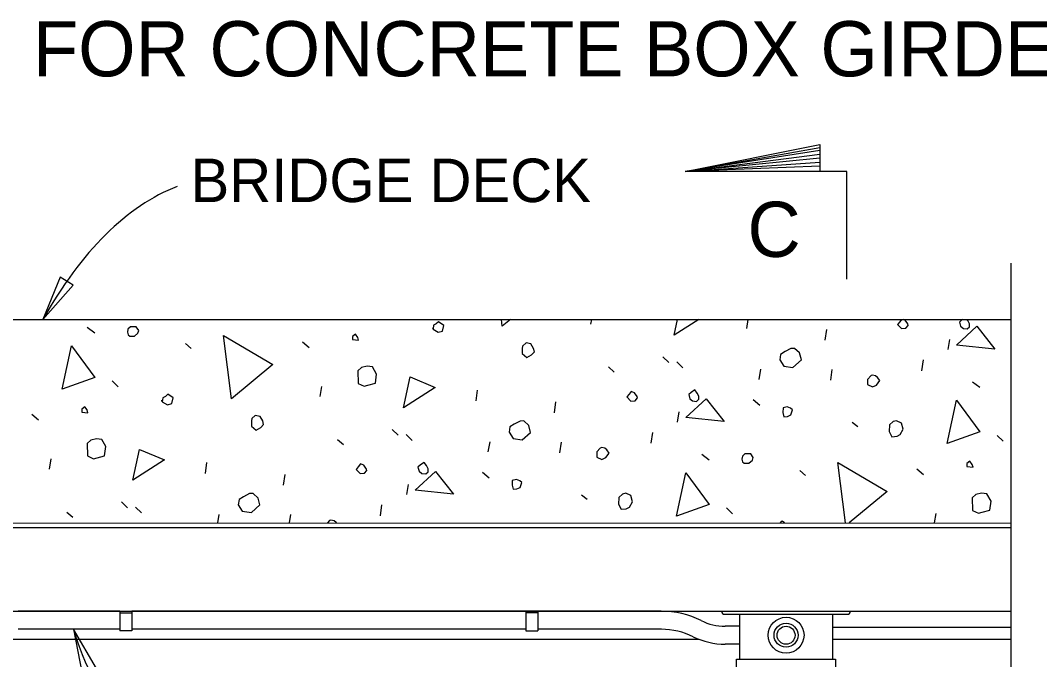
# Model space of a CAD drawing. Extents: x -1660015.2 to -1659984.9, y 2580594.2 to 2580616.7.
# Drawn here: x -1660010.005 to -1660006.46, y 2580602.872 to 2580605.097 of the extents above; entities that cross this region are included whole.
import ezdxf

# ---------------------------------------------------------------- set-up
doc = ezdxf.new("R2010")
doc.units = 0
for name, color, linetype in [('Default', 7, 'Continuous'), ('Miscellaneous', 7, 'Continuous'), ('Miscellaneous3', 7, 'Continuous'), ('PlotBorder_dp', 7, 'Continuous'), ('SheetLines_dp', 7, 'Continuous'), ('SteelGirder', 7, 'Continuous')]:
    doc.layers.add(name, color=color, linetype=linetype)

msp = doc.modelspace()

# ---------------------------------------------------------------- linework, layer by layer
at = {"layer": 'Default'}
for p, q in [((-1660009.6587, 2580603.0404), (-1660010.0129, 2580603.0404)), ((-1660008.2474, 2580603.0404), (-1660009.617, 2580603.0404)), ((-1660007.7757, 2580603.0404), (-1660008.2057, 2580603.0404)), ((-1660007.5656, 2580603.0404), (-1660007.1177, 2580603.0404)), ((-1660007.5031, 2580603.0404), (-1660007.1802, 2580603.0404)), ((-1660007.5552, 2580603.03), (-1660007.1281, 2580603.03)), ((-1660007.5031, 2580603.03), (-1660007.5031, 2580602.8737)), ((-1660007.1802, 2580603.03), (-1660007.1802, 2580602.8737)), ((-1660009.6587, 2580602.9779), (-1660010.013, 2580602.9779)), ((-1660008.2474, 2580602.9779), (-1660009.617, 2580602.9779)), ((-1660007.7752, 2580602.9779), (-1660008.2057, 2580602.9779)), ((-1660007.5031, 2580602.9883), (-1660007.5535, 2580602.9883)), ((-1660007.5031, 2580602.9258), (-1660007.5535, 2580602.9258)), ((-1660007.5135, 2580602.3841), (-1660007.5135, 2580602.8737)), ((-1660007.5135, 2580602.8737), (-1660007.5031, 2580602.8737)), ((-1660007.5031, 2580602.8737), (-1660007.1802, 2580602.8737)), ((-1660007.1802, 2580602.8737), (-1660007.1698, 2580602.8737)), ((-1660007.1698, 2580602.8737), (-1660007.1698, 2580602.3841))]:
    msp.add_line(p, q, dxfattribs=at)
for radius in [0.0625, 0.0417, 0.0312]:
    msp.add_circle((-1660007.3417, 2580602.957), radius, dxfattribs=at)
for centre, radius, start, end in [((-1660007.7757, 2580602.7279), 0.3125, 63.6115, 90.0001), ((-1660007.5552, 2580603.0404), 0.0104, 180, 270), ((-1660007.1281, 2580603.0404), 0.0104, 270, 0), ((-1660007.5535, 2580603.1758), 0.1875, 243.6115, 270), ((-1660007.7757, 2580602.7279), 0.25, 63.6115, 89.8816), ((-1660007.5535, 2580603.1758), 0.25, 243.6115, 270)]:
    msp.add_arc(centre, radius, start, end, dxfattribs=at)
at = {"layer": 'Miscellaneous'}
for p, q in [((-1660009.7723, 2580604.0286), (-1660009.7465, 2580604.0096)), ((-1660008.0205, 2580604.0399), (-1660008.0177, 2580604.056)), ((-1660007.4781, 2580604.0247), (-1660007.4736, 2580604.056)), ((-1660007.2057, 2580603.9838), (-1660007.2003, 2580604.0215)), ((-1660009.4311, 2580603.9725), (-1660009.4108, 2580603.9546)), ((-1660009.0237, 2580603.9781), (-1660009.0003, 2580603.9585)), ((-1660006.7777, 2580603.951), (-1660006.7716, 2580603.9863)), ((-1660007.77, 2580603.9258), (-1660007.749, 2580603.9056)), ((-1660007.9598, 2580603.8905), (-1660007.9395, 2580603.8726)), ((-1660007.7211, 2580603.9079), (-1660007.7002, 2580603.8876)), ((-1660007.4357, 2580603.8472), (-1660007.4296, 2580603.8824)), ((-1660007.1864, 2580603.8441), (-1660007.181, 2580603.8818)), ((-1660006.8692, 2580603.8773), (-1660006.8638, 2580603.915)), ((-1660009.6861, 2580603.842), (-1660009.6651, 2580603.8218)), ((-1660008.9623, 2580603.7875), (-1660008.9562, 2580603.8228)), ((-1660006.6933, 2580603.839), (-1660006.6675, 2580603.8201)), ((-1660008.4199, 2580603.7724), (-1660008.4145, 2580603.8101)), ((-1660007.4558, 2580603.7771), (-1660007.4324, 2580603.7575)), ((-1660008.1475, 2580603.7315), (-1660008.1421, 2580603.7692)), ((-1660009.9655, 2580603.7258), (-1660009.9421, 2580603.7061)), ((-1660007.7194, 2580603.6987), (-1660007.7134, 2580603.7339)), ((-1660008.7117, 2580603.6735), (-1660008.6908, 2580603.6532)), ((-1660007.1112, 2580603.6986), (-1660007.0915, 2580603.6831)), ((-1660008.9016, 2580603.6381), (-1660008.8813, 2580603.6203)), ((-1660008.6629, 2580603.6555), (-1660008.642, 2580603.6352)), ((-1660007.811, 2580603.625), (-1660007.8056, 2580603.6626)), ((-1660006.6071, 2580603.6525), (-1660006.5861, 2580603.6322)), ((-1660008.3775, 2580603.5948), (-1660008.3714, 2580603.6301)), ((-1660008.1282, 2580603.5917), (-1660008.1228, 2580603.6294)), ((-1660009.9041, 2580603.5352), (-1660009.898, 2580603.5704)), ((-1660007.6351, 2580603.5867), (-1660007.6093, 2580603.5677)), ((-1660009.3617, 2580603.52), (-1660009.3562, 2580603.5577)), ((-1660007.2939, 2580603.5306), (-1660007.2736, 2580603.5127)), ((-1660006.8865, 2580603.5362), (-1660006.8631, 2580603.5166)), ((-1660009.0893, 2580603.4791), (-1660009.0839, 2580603.5168)), ((-1660008.3975, 2580603.5247), (-1660008.3742, 2580603.5051)), ((-1660008.6612, 2580603.4463), (-1660008.6551, 2580603.4816)), ((-1660009.6535, 2580603.4211), (-1660009.6326, 2580603.4009)), ((-1660008.053, 2580603.4462), (-1660008.0333, 2580603.4308)), ((-1660009.8433, 2580603.3858), (-1660009.823, 2580603.3679)), ((-1660009.6047, 2580603.4032), (-1660009.5837, 2580603.3829)), ((-1660008.7528, 2580603.3726), (-1660008.7473, 2580603.4103)), ((-1660007.5489, 2580603.4001), (-1660007.5279, 2580603.3799)), ((-1660009.3184, 2580603.3477), (-1660009.3132, 2580603.3777)), ((-1660009.0688, 2580603.3477), (-1660009.0645, 2580603.3771)), ((-1660006.8247, 2580603.3477), (-1660006.819, 2580603.3809)), ((-1660011.3782, 2580603.3476), (-1660006.558, 2580603.3477)), ((-1660011.374, 2580603.332), (-1660006.558, 2580603.3321)), ((-1660012.0501, 2580603.0403), (-1660006.558, 2580603.0404))]:
    msp.add_line(p, q, dxfattribs=at)
for points in [[(-1660009.6305, 2580604.0019), (-1660009.6244, 2580603.9983), (-1660009.6086, 2580603.9974), (-1660009.5961, 2580604.0085), (-1660009.5932, 2580604.017), (-1660009.6019, 2580604.0302), (-1660009.6225, 2580604.0299), (-1660009.6309, 2580604.0225), (-1660009.6331, 2580604.0115), (-1660009.6305, 2580604.0019)], [(-1660008.5696, 2580604.0221), (-1660008.5513, 2580604.0115), (-1660008.5368, 2580604.0154), (-1660008.5316, 2580604.0349), (-1660008.5507, 2580604.0479), (-1660008.559, 2580604.0405), (-1660008.568, 2580604.0355), (-1660008.5696, 2580604.0221), (-1660008.5709, 2580604.027)], [(-1660008.3291, 2580604.0323), (-1660008.3321, 2580604.056)], [(-1660008.3003, 2580604.056), (-1660008.3291, 2580604.0323)], [(-1660007.7306, 2580604.0011), (-1660007.7188, 2580604.056)], [(-1660007.6453, 2580604.056), (-1660007.7306, 2580604.0011)], [(-1660006.9538, 2580604.0384), (-1660006.9396, 2580604.0241), (-1660006.9245, 2580604.0256), (-1660006.9167, 2580604.0354), (-1660006.918, 2580604.0402), (-1660006.9268, 2580604.0534), (-1660006.9331, 2580604.056)], [(-1660006.94, 2580604.056), (-1660006.9461, 2580604.0482), (-1660006.9538, 2580604.0384)], [(-1660006.7482, 2580603.9667), (-1660006.6778, 2580604.0321), (-1660006.6152, 2580603.9531), (-1660006.7482, 2580603.9667)], [(-1660006.7278, 2580604.056), (-1660006.7303, 2580604.0543), (-1660006.7387, 2580604.0469), (-1660006.7348, 2580604.0324)], [(-1660006.7348, 2580604.0324), (-1660006.7249, 2580604.0247), (-1660006.7116, 2580604.0231), (-1660006.7032, 2580604.0305), (-1660006.7034, 2580604.0408), (-1660006.709, 2580604.0522), (-1660006.7118, 2580604.056)], [(-1660009.2708, 2580603.7799), (-1660009.2988, 2580604.0002), (-1660009.1267, 2580603.8988), (-1660009.2708, 2580603.7799)], [(-1660008.8498, 2580603.9859), (-1660008.8285, 2580603.9838), (-1660008.8311, 2580603.9935), (-1660008.8392, 2580604.0043), (-1660008.85, 2580603.9962), (-1660008.8498, 2580603.9859)], [(-1660009.8596, 2580603.8137), (-1660009.8276, 2580603.9646), (-1660009.7463, 2580603.8544), (-1660009.8596, 2580603.8137)], [(-1660008.2592, 2580603.9552), (-1660008.2595, 2580603.937), (-1660008.2429, 2580603.9233), (-1660008.2273, 2580603.9327), (-1660008.2172, 2580603.9432), (-1660008.2204, 2580603.9552), (-1660008.2298, 2580603.9709), (-1660008.2462, 2580603.9742), (-1660008.2588, 2580603.9631), (-1660008.2592, 2580603.9552)], [(-1660007.3635, 2580603.9157), (-1660007.3498, 2580603.8935), (-1660007.3176, 2580603.8892), (-1660007.2883, 2580603.9151), (-1660007.2948, 2580603.9393), (-1660007.312, 2580603.9554), (-1660007.3247, 2580603.9545), (-1660007.3452, 2580603.9439), (-1660007.3608, 2580603.9345), (-1660007.3635, 2580603.9157)], [(-1660008.831, 2580603.8771), (-1660008.8297, 2580603.8334), (-1660008.8089, 2580603.8235), (-1660008.7968, 2580603.8267), (-1660008.7702, 2580603.8338), (-1660008.7659, 2580603.866), (-1660008.7803, 2580603.8906), (-1660008.7991, 2580603.8934), (-1660008.8184, 2580603.8882), (-1660008.831, 2580603.8771)], [(-1660008.6724, 2580603.7487), (-1660008.6493, 2580603.8559), (-1660008.562, 2580603.8197), (-1660008.6724, 2580603.7487)], [(-1660007.0579, 2580603.8475), (-1660007.0582, 2580603.8293), (-1660007.0405, 2580603.8211), (-1660007.0266, 2580603.8274), (-1660007.0154, 2580603.8433), (-1660007.0235, 2580603.8541), (-1660007.0302, 2580603.86), (-1660007.0412, 2580603.8623), (-1660007.046, 2580603.861), (-1660007.0579, 2580603.8475)], [(-1660009.5114, 2580603.7698), (-1660009.493, 2580603.7592), (-1660009.4786, 2580603.7631), (-1660009.4734, 2580603.7826), (-1660009.4924, 2580603.7956), (-1660009.5008, 2580603.7882), (-1660009.5098, 2580603.7832), (-1660009.5114, 2580603.7698), (-1660009.5127, 2580603.7746)], [(-1660007.8956, 2580603.7861), (-1660007.8814, 2580603.7717), (-1660007.8662, 2580603.7732), (-1660007.8585, 2580603.783), (-1660007.8598, 2580603.7879), (-1660007.8685, 2580603.8011), (-1660007.8801, 2580603.8057), (-1660007.8878, 2580603.7959), (-1660007.8956, 2580603.7861)], [(-1660007.69, 2580603.7143), (-1660007.6195, 2580603.7798), (-1660007.557, 2580603.7008), (-1660007.69, 2580603.7143)], [(-1660007.6765, 2580603.78), (-1660007.6667, 2580603.7723), (-1660007.6533, 2580603.7707), (-1660007.645, 2580603.7781), (-1660007.6452, 2580603.7885), (-1660007.6508, 2580603.7999), (-1660007.6589, 2580603.8107), (-1660007.6721, 2580603.8019), (-1660007.6804, 2580603.7945), (-1660007.6765, 2580603.78)], [(-1660009.7916, 2580603.7335), (-1660009.7703, 2580603.7315), (-1660009.7729, 2580603.7411), (-1660009.781, 2580603.7519), (-1660009.7918, 2580603.7439), (-1660009.7916, 2580603.7335)], [(-1660007.3531, 2580603.7321), (-1660007.3492, 2580603.7176), (-1660007.3365, 2580603.7184), (-1660007.3251, 2580603.7241), (-1660007.3193, 2580603.7412), (-1660007.3261, 2580603.7471), (-1660007.3377, 2580603.7518), (-1660007.3522, 2580603.7479), (-1660007.3531, 2580603.7321)], [(-1660006.7807, 2580603.6241), (-1660006.7486, 2580603.775), (-1660006.6673, 2580603.6648), (-1660006.7807, 2580603.6241)], [(-1660009.201, 2580603.7028), (-1660009.2013, 2580603.6847), (-1660009.1847, 2580603.671), (-1660009.1691, 2580603.6803), (-1660009.159, 2580603.6908), (-1660009.1622, 2580603.7029), (-1660009.1716, 2580603.7185), (-1660009.188, 2580603.7219), (-1660009.2005, 2580603.7107), (-1660009.201, 2580603.7028)], [(-1660008.3053, 2580603.6633), (-1660008.2915, 2580603.6411), (-1660008.2593, 2580603.6368), (-1660008.2301, 2580603.6628), (-1660008.2365, 2580603.6869), (-1660008.2538, 2580603.703), (-1660008.2665, 2580603.7022), (-1660008.2869, 2580603.6915), (-1660008.3025, 2580603.6822), (-1660008.3053, 2580603.6633)], [(-1660006.9819, 2580603.6892), (-1660006.9833, 2580603.6656), (-1660006.9733, 2580603.6475), (-1660006.9557, 2580603.6497), (-1660006.9443, 2580603.6553), (-1660006.9337, 2580603.6737), (-1660006.9395, 2580603.6954), (-1660006.9573, 2580603.7036), (-1660006.9693, 2580603.7004), (-1660006.9819, 2580603.6892)], [(-1660009.7728, 2580603.6247), (-1660009.7714, 2580603.5811), (-1660009.7506, 2580603.5711), (-1660009.7386, 2580603.5743), (-1660009.712, 2580603.5815), (-1660009.7077, 2580603.6137), (-1660009.7221, 2580603.6383), (-1660009.7409, 2580603.641), (-1660009.7602, 2580603.6358), (-1660009.7728, 2580603.6247)], [(-1660009.6142, 2580603.4964), (-1660009.5911, 2580603.6035), (-1660009.5038, 2580603.5674), (-1660009.6142, 2580603.4964)], [(-1660007.9997, 2580603.5951), (-1660008, 2580603.5769), (-1660007.9823, 2580603.5687), (-1660007.9684, 2580603.575), (-1660007.9572, 2580603.591), (-1660007.9652, 2580603.6017), (-1660007.972, 2580603.6077), (-1660007.983, 2580603.6099), (-1660007.9878, 2580603.6086), (-1660007.9997, 2580603.5951)], [(-1660007.4933, 2580603.56), (-1660007.4872, 2580603.5564), (-1660007.4714, 2580603.5555), (-1660007.4589, 2580603.5666), (-1660007.456, 2580603.5751), (-1660007.4647, 2580603.5883), (-1660007.4853, 2580603.588), (-1660007.4937, 2580603.5806), (-1660007.4959, 2580603.5696), (-1660007.4933, 2580603.56)], [(-1660008.8373, 2580603.5337), (-1660008.8232, 2580603.5194), (-1660008.808, 2580603.5209), (-1660008.8003, 2580603.5307), (-1660008.8016, 2580603.5355), (-1660008.8103, 2580603.5487), (-1660008.8219, 2580603.5534), (-1660008.8296, 2580603.5435), (-1660008.8373, 2580603.5337)], [(-1660008.6318, 2580603.462), (-1660008.5613, 2580603.5274), (-1660008.4987, 2580603.4484), (-1660008.6318, 2580603.462)], [(-1660008.6183, 2580603.5277), (-1660008.6085, 2580603.52), (-1660008.5951, 2580603.5184), (-1660008.5868, 2580603.5258), (-1660008.5869, 2580603.5361), (-1660008.5926, 2580603.5475), (-1660008.6006, 2580603.5583), (-1660008.6138, 2580603.5496), (-1660008.6222, 2580603.5422), (-1660008.6183, 2580603.5277)], [(-1660007.1349, 2580603.3477), (-1660007.1616, 2580603.5583), (-1660006.9895, 2580603.4569), (-1660007.1219, 2580603.3477)], [(-1660006.7126, 2580603.544), (-1660006.6913, 2580603.5419), (-1660006.6939, 2580603.5516), (-1660006.702, 2580603.5624), (-1660006.7128, 2580603.5543), (-1660006.7126, 2580603.544)], [(-1660008.2949, 2580603.4798), (-1660008.291, 2580603.4653), (-1660008.2783, 2580603.4661), (-1660008.2669, 2580603.4717), (-1660008.2611, 2580603.4888), (-1660008.2679, 2580603.4948), (-1660008.2795, 2580603.4994), (-1660008.294, 2580603.4955), (-1660008.2949, 2580603.4798)], [(-1660007.7224, 2580603.3717), (-1660007.6904, 2580603.5227), (-1660007.6091, 2580603.4125), (-1660007.7224, 2580603.3717)], [(-1660009.247, 2580603.411), (-1660009.2333, 2580603.3888), (-1660009.2011, 2580603.3845), (-1660009.1718, 2580603.4104), (-1660009.1783, 2580603.4346), (-1660009.1956, 2580603.4507), (-1660009.2083, 2580603.4498), (-1660009.2287, 2580603.4392), (-1660009.2443, 2580603.4298), (-1660009.247, 2580603.411)], [(-1660007.9237, 2580603.4369), (-1660007.9251, 2580603.4132), (-1660007.9151, 2580603.3952), (-1660007.8975, 2580603.3973), (-1660007.8861, 2580603.403), (-1660007.8755, 2580603.4213), (-1660007.8813, 2580603.4431), (-1660007.899, 2580603.4513), (-1660007.9111, 2580603.448), (-1660007.9237, 2580603.4369)], [(-1660006.6938, 2580603.4351), (-1660006.6925, 2580603.3915), (-1660006.6717, 2580603.3815), (-1660006.6596, 2580603.3848), (-1660006.633, 2580603.3919), (-1660006.6287, 2580603.4241), (-1660006.6431, 2580603.4487), (-1660006.6619, 2580603.4514), (-1660006.6812, 2580603.4463), (-1660006.6938, 2580603.4351)], [(-1660008.9057, 2580603.3477), (-1660008.907, 2580603.3494), (-1660008.9138, 2580603.3553), (-1660008.9247, 2580603.3576), (-1660008.9296, 2580603.3563), (-1660008.9372, 2580603.3477)], [(-1660007.3465, 2580603.3477), (-1660007.3552, 2580603.3537), (-1660007.362, 2580603.3477)]]:
    msp.add_lwpolyline(points, dxfattribs=at)
at = {"layer": 'Miscellaneous3'}
msp.add_line((-1660015.0462, 2580604.0559), (-1660006.558, 2580604.056), dxfattribs=at)
at = {"layer": 'SheetLines_dp'}
for p, q in [((-1660007.6927, 2580604.5713), (-1660007.224, 2580604.6538)), ((-1660007.224, 2580604.6438), (-1660007.6927, 2580604.5713)), ((-1660007.6927, 2580604.5713), (-1660007.224, 2580604.6313)), ((-1660007.224, 2580604.6176), (-1660007.6927, 2580604.5713)), ((-1660007.6927, 2580604.5713), (-1660007.224, 2580604.6038)), ((-1660007.224, 2580604.5888), (-1660007.6927, 2580604.5713))]:
    msp.add_line(p, q, dxfattribs=at)
for points in [[(-1660007.1303, 2580604.1963), (-1660007.1303, 2580604.5713), (-1660007.6927, 2580604.5713), (-1660007.224, 2580604.6651), (-1660007.224, 2580604.5713)], [(-1660006.558, 2580601.9272), (-1660006.558, 2580604.252)]]:
    msp.add_lwpolyline(points, dxfattribs=at)
for points in [[(-1660009.9267, 2580604.0559), (-1660009.8221, 2580604.1748), (-1660009.8671, 2580604.2026)], [(-1660009.8205, 2580602.9778), (-1660009.7901, 2580602.8223), (-1660009.7406, 2580602.841)]]:
    msp.add_lwpolyline(points, close=True, dxfattribs=at)
for centre, major_axis, ratio, start_param, end_param in [((-1660009.1816, 2580602.1871), (0.1111, -2.3674), 0.464296, 3.295381, 3.781059), ((-1660009.5408, 2580603.775), (0.079, 1.0703), 0.315754, 2.434073, 3.141613)]:
    msp.add_ellipse(centre, major_axis=major_axis, ratio=ratio, start_param=start_param, end_param=end_param, dxfattribs=at)
at = {"layer": 'SteelGirder'}
for p, q in [((-1660009.6587, 2580603.0404), (-1660009.6587, 2580602.9727)), ((-1660009.6587, 2580603.0404), (-1660009.617, 2580603.0404)), ((-1660009.6587, 2580603.0352), (-1660009.617, 2580603.0352)), ((-1660009.617, 2580603.0404), (-1660009.617, 2580602.9727)), ((-1660008.2474, 2580603.0404), (-1660008.2474, 2580602.9727)), ((-1660008.2057, 2580603.0404), (-1660008.2474, 2580603.0404)), ((-1660008.2057, 2580603.0352), (-1660008.2474, 2580603.0352)), ((-1660008.2057, 2580603.0404), (-1660008.2057, 2580602.9727)), ((-1660009.617, 2580602.9727), (-1660009.6587, 2580602.9727)), ((-1660008.2474, 2580602.9727), (-1660008.2057, 2580602.9727)), ((-1660007.1803, 2580602.9854), (-1660006.558, 2580602.9854)), ((-1660010.1415, 2580602.9437), (-1660007.6465, 2580602.9437)), ((-1660007.1803, 2580602.9437), (-1660006.558, 2580602.9437))]:
    msp.add_line(p, q, dxfattribs=at)

# ---------------------------------------------------------------- texts
at = {"layer": 'PlotBorder_dp'}
for s, height, p in [('LIGHTING DETAILS FOR CONCRETE BOX GIRDER BRIDGE', 0.192, (-1660012.3863, 2580604.9018)), ('BRIDGE DECK', 0.1512, (-1660009.4134, 2580604.4644)), ('C', 0.192, (-1660007.476, 2580604.2736))]:
    msp.add_text(s, height=height, dxfattribs=at).set_placement(p)

doc.saveas('drawing.dxf')
